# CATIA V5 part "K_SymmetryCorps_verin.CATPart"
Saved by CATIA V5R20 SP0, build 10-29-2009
Part number: Symmetry of Corps_verin
Bounding box of the stored display mesh (mm): x -11 to 23.5, y -11.046 to 15.42, z -205.19 to 7.233
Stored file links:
  G:\Khaled_CFAO_2011\SIL\SIL_GR2\zthiebault\Khaled\CAD_ThinkMOTION\K_SymmetryCorps_verin.CATPart
  G:\Khaled_CFAO_2011\SIL\SIL_GR2\zthiebault\Khaled\CAD_ThinkMOTION\K_Corps_verin.CATPart
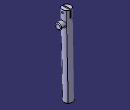
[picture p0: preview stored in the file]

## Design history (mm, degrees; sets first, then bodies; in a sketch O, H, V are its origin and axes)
Body1 (main body)
  Body2 "Corps du corps principal d'origine"
    Solid1: linked copy from another document
  Assemble1: tool Body2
